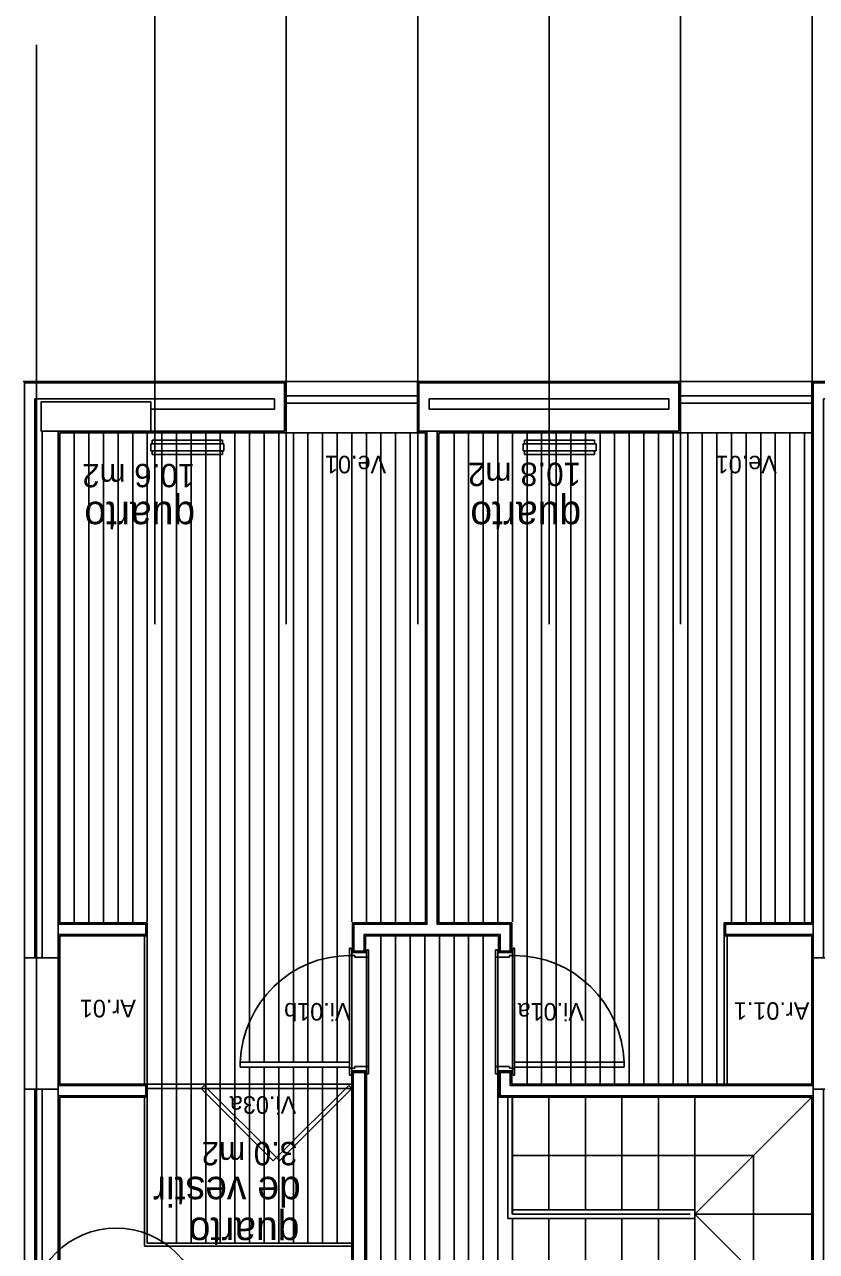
# Model space of a CAD drawing. Extents: x 1278 to 1356, y -253.7 to -224.
# Drawn here: x 1329.2 to 1334.62, y -237.88 to -229.48 of the extents above; entities that cross this region are included whole.
import ezdxf

# ---------------------------------------------------------------- set-up
doc = ezdxf.new("R2010")
doc.units = 0
for name, color, linetype in [('Level 1', 7, 'Continuous'), ('Level 10', 7, 'Continuous'), ('Level 13', 7, 'Continuous'), ('Level 2', 7, 'Continuous'), ('Level 4', 7, 'Continuous'), ('Level 40', 7, 'Continuous'), ('Level 60', 7, 'Continuous'), ('Level 65', 7, 'Continuous'), ('Level 66', 7, 'Continuous'), ('Level 67', 7, 'Continuous'), ('Level 69', 7, 'Continuous'), ('Level 70', 7, 'Continuous'), ('Level 93', 7, 'Continuous')]:
    doc.layers.add(name, color=color, linetype=linetype)

msp = doc.modelspace()

# ---------------------------------------------------------------- linework, layer by layer
at = {"layer": 'Level 1'}
for p, q in [((1330.9825, -231.934), (1330.9825, -232.2657)), ((1329.2718, -232.044), (1329.2718, -235.8713)), ((1330.9125, -232.1143), (1330.0668, -232.1143)), ((1330.9125, -232.044), (1330.9125, -232.1143)), ((1329.4325, -246.584), (1329.4325, -232.2657)), ((1330.9825, -232.2657), (1329.4325, -232.2657)), ((1331.9575, -232.2657), (1331.9575, -235.6407)), ((1332.0275, -235.6407), (1332.0275, -232.2657)), ((1330.0325, -235.6407), (1329.4325, -235.6407)), ((1330.0325, -235.7107), (1330.0325, -235.6407)), ((1331.9575, -235.6407), (1331.4575, -235.6407)), ((1331.4575, -235.6407), (1331.4575, -235.8257)), ((1332.5275, -235.6407), (1332.0275, -235.6407)), ((1332.5275, -235.8257), (1332.5275, -235.6407)), ((1334.6025, -235.6407), (1334.0025, -235.6407)), ((1334.0025, -235.6407), (1334.0025, -235.7107)), ((1329.4325, -235.7107), (1330.0325, -235.7107)), ((1331.5275, -235.7107), (1332.4575, -235.7107)), ((1331.5275, -235.8257), (1331.5275, -235.7107)), ((1332.4575, -235.7107), (1332.4575, -235.8257)), ((1334.0025, -235.7107), (1334.6025, -235.7107)), ((1331.4475, -235.8257), (1331.5375, -235.8257)), ((1332.5375, -235.8257), (1332.4475, -235.8257)), ((1331.4425, -236.6557), (1331.5425, -236.6557)), ((1331.4525, -236.6557), (1331.4525, -238.4357)), ((1331.5325, -238.4357), (1331.5325, -236.6557)), ((1332.5375, -236.6557), (1332.4475, -236.6557)), ((1332.4575, -236.6557), (1332.4575, -236.8157)), ((1332.5275, -236.6557), (1332.5275, -236.7457)), ((1329.2718, -236.7713), (1329.2718, -242.1713)), ((1329.3225, -242.1713), (1329.3225, -236.7713)), ((1330.0325, -236.7457), (1329.4325, -236.7457)), ((1329.4325, -236.8157), (1330.0325, -236.8157)), ((1330.0325, -236.8157), (1330.0325, -236.7457)), ((1332.4575, -236.8157), (1334.6025, -236.8157)), ((1332.5275, -236.7457), (1334.6025, -236.7457))]:
    msp.add_line(p, q, dxfattribs=at)
at = {"layer": 'Level 10'}
for p, q in [((1329.5425, -232.2757), (1329.5425, -235.6307)), ((1329.6425, -232.2757), (1329.6425, -235.6307)), ((1329.7425, -232.2757), (1329.7425, -235.6307)), ((1329.8425, -232.2757), (1329.8425, -235.6307)), ((1329.9425, -232.2757), (1329.9425, -235.6307)), ((1330.0425, -232.2757), (1330.0425, -235.6257)), ((1330.1425, -232.2757), (1330.1425, -237.8257)), ((1330.2425, -232.2757), (1330.2425, -237.8257)), ((1330.3425, -232.2757), (1330.3425, -237.8257)), ((1330.4425, -232.2757), (1330.4425, -237.8257)), ((1330.5425, -232.2757), (1330.5425, -237.8257)), ((1330.6425, -232.2757), (1330.6425, -237.8257)), ((1330.7425, -232.2757), (1330.7425, -236.5857)), ((1330.8425, -232.2757), (1330.8425, -236.5857)), ((1330.9425, -232.2757), (1330.9425, -236.5857)), ((1331.0425, -232.2757), (1331.0425, -236.5857)), ((1331.1425, -232.2757), (1331.1425, -236.5857)), ((1331.2425, -232.2757), (1331.2425, -236.5857)), ((1331.3425, -232.2757), (1331.3425, -236.5857)), ((1331.4425, -232.2757), (1331.4425, -235.6257)), ((1331.5425, -232.2757), (1331.5425, -235.6257)), ((1331.6425, -232.2757), (1331.6425, -235.6257)), ((1331.7425, -232.2757), (1331.7425, -235.6257)), ((1331.8425, -232.2757), (1331.8425, -235.6257)), ((1332.1425, -235.6257), (1332.1425, -232.2757)), ((1332.2425, -235.6257), (1332.2425, -232.2757)), ((1332.3425, -235.6257), (1332.3425, -232.2757)), ((1332.4425, -235.6257), (1332.4425, -232.2757)), ((1332.5425, -235.6257), (1332.5425, -232.2757)), ((1332.6425, -232.2757), (1332.6425, -236.7357)), ((1332.7425, -232.2757), (1332.7425, -236.7357)), ((1332.8425, -232.2757), (1332.8425, -236.7357)), ((1332.9425, -232.2757), (1332.9425, -236.7357)), ((1333.0425, -232.2757), (1333.0425, -236.7357)), ((1333.1425, -232.2757), (1333.1425, -236.7357)), ((1333.2425, -232.2757), (1333.2425, -236.7357)), ((1333.3425, -232.2757), (1333.3425, -236.7357)), ((1333.4425, -232.2757), (1333.4425, -236.7357)), ((1333.5425, -232.2757), (1333.5425, -236.7357)), ((1333.6425, -232.2757), (1333.6425, -236.7357)), ((1333.7425, -232.2757), (1333.7425, -236.7357)), ((1333.8425, -232.2757), (1333.8425, -236.7357)), ((1333.9425, -232.2757), (1333.9425, -236.7357)), ((1334.0425, -232.2757), (1334.0425, -235.6257)), ((1334.1425, -232.2757), (1334.1425, -235.6257)), ((1334.2425, -232.2757), (1334.2425, -235.6257)), ((1334.3425, -232.2757), (1334.3425, -235.6257)), ((1334.4425, -232.2757), (1334.4425, -235.6257)), ((1334.5425, -232.2757), (1334.5425, -235.6257)), ((1331.6425, -235.7207), (1331.6425, -238.4107)), ((1331.7425, -235.7207), (1331.7425, -238.4257)), ((1331.8425, -235.7207), (1331.8425, -238.4257)), ((1331.9425, -235.7207), (1331.9425, -238.4257)), ((1332.0425, -235.7207), (1332.0425, -238.4257)), ((1332.1425, -235.7207), (1332.1425, -238.4257)), ((1332.2425, -235.7207), (1332.2425, -238.4257)), ((1332.3425, -235.7207), (1332.3425, -238.4107)), ((1331.4425, -235.8557), (1331.4425, -236.6257)), ((1331.5425, -235.8657), (1331.5425, -236.6157)), ((1332.4425, -235.8657), (1332.4425, -236.6157)), ((1332.5425, -235.8557), (1332.5425, -236.6257)), ((1330.7425, -236.6207), (1330.7425, -237.8257)), ((1330.8425, -236.6207), (1330.8425, -237.8257)), ((1330.9425, -236.6207), (1330.9425, -237.8257)), ((1331.0425, -236.6207), (1331.0425, -237.8257)), ((1331.1425, -236.6207), (1331.1425, -237.8257)), ((1331.2425, -236.6207), (1331.2425, -237.8257)), ((1331.3425, -236.6207), (1331.3425, -237.8257)), ((1332.4425, -236.6557), (1332.4425, -238.4257))]:
    msp.add_line(p, q, dxfattribs=at)
at = {"layer": 'Level 13'}
for p, q in [((1330.0225, -236.7357), (1330.0225, -235.7207)), ((1330.0425, -236.7357), (1330.0425, -235.7207)), ((1333.9925, -236.7357), (1333.9925, -235.7207)), ((1334.0125, -236.7357), (1334.0125, -235.7207)), ((1331.4275, -235.8057), (1331.4275, -235.8557)), ((1331.4375, -235.8057), (1331.4275, -235.8057)), ((1331.4375, -235.8107), (1331.4375, -235.8057)), ((1331.4425, -235.8107), (1331.4375, -235.8107)), ((1331.4425, -235.8557), (1331.4425, -235.8107)), ((1331.5425, -235.8657), (1331.5425, -235.8207)), ((1331.5425, -235.8207), (1331.5475, -235.8207)), ((1331.5475, -235.8207), (1331.5475, -235.8157)), ((1331.5475, -235.8157), (1331.5575, -235.8157)), ((1331.5575, -235.8157), (1331.5575, -235.8657)), ((1332.4275, -235.8157), (1332.4275, -235.8657)), ((1332.4375, -235.8157), (1332.4275, -235.8157)), ((1332.4375, -235.8207), (1332.4375, -235.8157)), ((1332.4425, -235.8207), (1332.4375, -235.8207)), ((1332.4425, -235.8657), (1332.4425, -235.8207)), ((1332.5425, -235.8557), (1332.5425, -235.8107)), ((1332.5425, -235.8107), (1332.5475, -235.8107)), ((1332.5475, -235.8107), (1332.5475, -235.8057)), ((1332.5475, -235.8057), (1332.5575, -235.8057)), ((1332.5575, -235.8057), (1332.5575, -235.8557)), ((1331.4275, -235.8557), (1331.4425, -235.8557)), ((1331.4425, -235.8357), (1331.5425, -235.8357)), ((1331.4425, -235.8557), (1331.4425, -235.8357)), ((1331.4625, -235.8557), (1331.4425, -235.8557)), ((1331.4625, -235.8657), (1331.4625, -235.8557)), ((1331.5425, -235.8657), (1331.4625, -235.8657)), ((1331.5425, -235.8357), (1331.5425, -235.8657)), ((1331.5575, -235.8657), (1331.5425, -235.8657)), ((1332.4275, -235.8657), (1332.4425, -235.8657)), ((1332.5425, -235.8357), (1332.4425, -235.8357)), ((1332.4425, -235.8357), (1332.4425, -235.8657)), ((1332.4425, -235.8657), (1332.5225, -235.8657)), ((1332.5225, -235.8657), (1332.5225, -235.8557)), ((1332.5225, -235.8557), (1332.5425, -235.8557)), ((1332.5425, -235.8557), (1332.5425, -235.8357)), ((1332.5575, -235.8557), (1332.5425, -235.8557)), ((1331.4275, -236.5857), (1330.6775, -236.5857)), ((1330.6775, -236.5857), (1330.6775, -236.6207)), ((1330.6775, -236.6207), (1331.4275, -236.6207)), ((1331.4275, -236.6207), (1331.4275, -236.5857)), ((1331.4275, -236.6757), (1331.4275, -236.6257)), ((1331.4275, -236.6257), (1331.4425, -236.6257)), ((1331.4625, -236.6257), (1331.4425, -236.6257)), ((1331.4425, -236.6257), (1331.4425, -236.6457)), ((1331.4425, -236.6257), (1331.4425, -236.6707)), ((1331.4425, -236.6457), (1331.5425, -236.6457)), ((1331.5425, -236.6157), (1331.4625, -236.6157)), ((1331.4625, -236.6157), (1331.4625, -236.6257)), ((1331.5425, -236.6457), (1331.5425, -236.6157)), ((1331.5575, -236.6157), (1331.5425, -236.6157)), ((1331.5425, -236.6157), (1331.5425, -236.6607)), ((1331.5425, -236.6607), (1331.5475, -236.6607)), ((1331.5475, -236.6607), (1331.5475, -236.6657)), ((1331.5575, -236.6657), (1331.5575, -236.6157)), ((1332.4275, -236.6657), (1332.4275, -236.6157)), ((1332.4275, -236.6157), (1332.4425, -236.6157)), ((1332.4425, -236.6607), (1332.4375, -236.6607)), ((1332.4375, -236.6607), (1332.4375, -236.6657)), ((1332.4425, -236.6157), (1332.4425, -236.6607)), ((1332.4425, -236.6457), (1332.4425, -236.6157)), ((1332.4425, -236.6157), (1332.5225, -236.6157)), ((1332.5425, -236.6457), (1332.4425, -236.6457)), ((1332.5225, -236.6157), (1332.5225, -236.6257)), ((1332.5225, -236.6257), (1332.5425, -236.6257)), ((1332.5425, -236.6257), (1332.5425, -236.6457)), ((1332.5575, -236.6257), (1332.5425, -236.6257)), ((1332.5425, -236.6257), (1332.5425, -236.6707)), ((1332.5575, -236.6207), (1332.5575, -236.5857)), ((1332.5575, -236.5857), (1333.3075, -236.5857)), ((1333.3075, -236.6207), (1332.5575, -236.6207)), ((1332.5575, -236.6757), (1332.5575, -236.6257)), ((1333.3075, -236.5857), (1333.3075, -236.6207)), ((1330.4102, -236.7657), (1330.4314, -236.7445)), ((1330.4314, -236.7445), (1330.9264, -237.2395)), ((1331.4213, -236.7445), (1330.9264, -237.2395)), ((1331.4425, -236.7657), (1331.4213, -236.7445)), ((1331.4375, -236.6757), (1331.4275, -236.6757)), ((1331.4425, -236.6707), (1331.4375, -236.6707)), ((1331.4375, -236.6707), (1331.4375, -236.6757)), ((1331.5475, -236.6657), (1331.5575, -236.6657)), ((1332.4375, -236.6657), (1332.4275, -236.6657)), ((1332.5425, -236.6707), (1332.5475, -236.6707)), ((1332.5475, -236.6707), (1332.5475, -236.6757)), ((1332.5475, -236.6757), (1332.5575, -236.6757)), ((1330.0225, -237.8457), (1330.0225, -236.8257)), ((1330.0425, -237.8257), (1330.0425, -236.8257)), ((1330.4102, -236.7657), (1330.9051, -237.2607)), ((1331.4425, -236.7657), (1330.9476, -237.2607)), ((1330.9051, -237.2607), (1330.9264, -237.2395)), ((1330.9476, -237.2607), (1330.9264, -237.2395)), ((1331.4425, -237.8257), (1330.0425, -237.8257)), ((1331.4425, -237.8457), (1330.0225, -237.8457))]:
    msp.add_line(p, q, dxfattribs=at)
at = {"layer": 'Level 2'}
for p, q in [((1331.8925, -231.924), (1330.9925, -231.924)), ((1334.5925, -231.924), (1333.6925, -231.924)), ((1331.8925, -232.024), (1330.9925, -232.024)), ((1334.5925, -232.024), (1333.6925, -232.024)), ((1331.8925, -232.074), (1330.9925, -232.074)), ((1334.5925, -232.074), (1333.6925, -232.074)), ((1331.8925, -232.2757), (1330.9925, -232.2757)), ((1334.5925, -232.2757), (1333.6925, -232.2757)), ((1332.5118, -237.6557), (1332.5118, -236.8257)), ((1332.5418, -237.6257), (1332.5418, -236.8257)), ((1332.5425, -237.6257), (1332.5425, -236.8257)), ((1332.7925, -237.5957), (1332.7925, -236.8257)), ((1333.0425, -237.5957), (1333.0425, -236.8257)), ((1333.2925, -237.5957), (1333.2925, -236.8257)), ((1333.5425, -237.5957), (1333.5425, -236.8257)), ((1333.7925, -237.5957), (1333.7925, -236.8257)), ((1333.7925, -237.6257), (1334.5925, -236.8257)), ((1332.5425, -237.2257), (1334.1925, -237.2257)), ((1334.1925, -238.0257), (1334.1925, -237.2257)), ((1333.7925, -237.6557), (1332.5118, -237.6557)), ((1333.7925, -237.5957), (1332.5425, -237.5957)), ((1333.7605, -237.6257), (1332.5425, -237.6257)), ((1332.5425, -238.424), (1332.5425, -237.6557)), ((1332.7925, -238.424), (1332.7925, -237.654)), ((1333.0425, -238.424), (1333.0425, -237.654)), ((1333.2925, -237.654), (1333.2925, -238.424)), ((1333.5425, -237.654), (1333.5425, -238.424)), ((1333.7925, -237.6557), (1333.7925, -237.5957)), ((1334.5925, -237.6257), (1333.7925, -237.6257)), ((1333.7925, -237.6257), (1334.5925, -238.4257)), ((1333.7925, -238.4257), (1333.7925, -237.6557))]:
    msp.add_line(p, q, dxfattribs=at)
at = {"layer": 'Level 4'}
for p, q in [((1331.4275, -235.8557), (1331.4275, -236.5857)), ((1331.5575, -236.6157), (1331.5575, -235.8657)), ((1332.4275, -236.6157), (1332.4275, -235.8657)), ((1332.5575, -235.8557), (1332.5575, -236.5857)), ((1330.0425, -236.7357), (1331.4425, -236.7357)), ((1330.0425, -236.7657), (1331.4425, -236.7657))]:
    msp.add_line(p, q, dxfattribs=at)
for centre, start_param, end_param in [((1331.4275, -236.6189), 3.141593, 4.668897), ((1332.5575, -236.6189), 1.614288, 3.141593)]:
    msp.add_ellipse(centre, major_axis=(0, -0.7632), ratio=0.982661, start_param=start_param, end_param=end_param, dxfattribs=at)
at = {"layer": 'Level 65'}
for p, q in [((1330.9925, -231.924), (1329.1918, -231.924)), ((1330.9925, -231.924), (1330.9925, -232.2757)), ((1331.8925, -232.2757), (1331.8925, -231.924)), ((1333.6925, -231.924), (1331.8925, -231.924)), ((1333.6925, -231.924), (1333.6925, -232.2757)), ((1336.3933, -231.924), (1334.5925, -231.924)), ((1334.5925, -235.6307), (1334.5925, -231.924)), ((1330.9925, -232.2757), (1329.4425, -232.2757)), ((1329.4425, -235.6307), (1329.4425, -232.2757)), ((1331.9475, -232.2757), (1331.8925, -232.2757)), ((1331.9475, -232.2757), (1331.9475, -235.6307)), ((1332.0375, -235.6307), (1332.0375, -232.2757)), ((1333.6925, -232.2757), (1332.0375, -232.2757)), ((1330.0425, -235.6307), (1329.4425, -235.6307)), ((1330.0425, -235.7207), (1330.0425, -235.6307)), ((1331.9475, -235.6307), (1331.4475, -235.6307)), ((1331.4475, -235.6307), (1331.4475, -235.8257)), ((1332.5375, -235.6307), (1332.0375, -235.6307)), ((1332.5375, -235.8257), (1332.5375, -235.6307)), ((1334.5925, -235.6307), (1333.9925, -235.6307)), ((1333.9925, -235.6307), (1333.9925, -235.7207)), ((1329.4425, -236.7357), (1329.4425, -235.7207)), ((1329.4425, -235.7207), (1330.0425, -235.7207)), ((1331.5375, -235.8257), (1331.5375, -235.7207)), ((1331.5375, -235.7207), (1332.4475, -235.7207)), ((1332.4475, -235.7207), (1332.4475, -235.8257)), ((1333.9925, -235.7207), (1334.5925, -235.7207)), ((1334.5925, -236.7357), (1334.5925, -235.7207)), ((1334.5925, -236.7357), (1334.5925, -235.7207)), ((1331.4425, -236.6557), (1331.4425, -238.4257)), ((1331.5425, -238.4257), (1331.5425, -236.6557)), ((1332.4475, -236.6557), (1332.4475, -236.8257)), ((1332.5375, -236.6557), (1332.5375, -236.7357)), ((1330.0425, -236.7357), (1329.4425, -236.7357)), ((1330.0425, -236.8257), (1330.0425, -236.7357)), ((1334.5925, -236.7357), (1332.5375, -236.7357)), ((1329.4425, -236.8257), (1330.0425, -236.8257)), ((1332.4475, -236.8257), (1334.5925, -236.8257)), ((1334.5925, -238.4257), (1334.5925, -236.8257)), ((1334.5925, -238.4257), (1334.5925, -236.8257))]:
    msp.add_line(p, q, dxfattribs=at)
msp.add_lwpolyline([(1329.4425, -238.164), (1329.4425, -236.8257)], dxfattribs=at)
at = {"layer": 'Level 66'}
for p, q in [((1330.9825, -231.934), (1329.2018, -231.934)), ((1333.6825, -231.934), (1331.9025, -231.934)), ((1331.9025, -231.934), (1331.9025, -232.2657)), ((1333.6825, -232.2657), (1333.6825, -231.934)), ((1336.3833, -231.934), (1334.6025, -231.934)), ((1334.6025, -235.6407), (1334.6025, -231.934)), ((1330.9125, -232.044), (1329.2718, -232.044)), ((1330.0668, -232.0639), (1329.3168, -232.0639)), ((1329.3168, -232.0639), (1329.3168, -232.2657)), ((1330.0668, -232.1143), (1330.0668, -232.0639)), ((1331.9725, -232.114), (1331.9725, -232.044)), ((1331.9725, -232.044), (1333.6125, -232.044)), ((1333.6125, -232.114), (1331.9725, -232.114)), ((1333.6125, -232.044), (1333.6125, -232.114)), ((1329.3225, -235.8713), (1329.3225, -232.2657)), ((1331.9025, -232.2657), (1333.6825, -232.2657)), ((1330.5668, -232.3507), (1330.0668, -232.3507)), ((1330.0668, -232.4007), (1330.0668, -232.3507)), ((1330.5568, -232.3257), (1330.0768, -232.3257)), ((1330.0768, -232.3507), (1330.0768, -232.3257)), ((1330.5568, -232.3507), (1330.5568, -232.3257)), ((1330.5668, -232.4007), (1330.5668, -232.3507)), ((1333.115, -232.3507), (1332.615, -232.3507)), ((1332.615, -232.4007), (1332.615, -232.3507)), ((1333.105, -232.3257), (1332.625, -232.3257)), ((1332.625, -232.3507), (1332.625, -232.3257)), ((1333.105, -232.3507), (1333.105, -232.3257)), ((1333.115, -232.4007), (1333.115, -232.3507)), ((1330.5668, -232.4007), (1330.0668, -232.4007)), ((1330.0768, -232.4257), (1330.0768, -232.4007)), ((1330.0768, -232.4257), (1330.5568, -232.4257)), ((1330.5568, -232.4257), (1330.5568, -232.4007)), ((1333.115, -232.4007), (1332.615, -232.4007)), ((1332.625, -232.4257), (1332.625, -232.4007)), ((1332.625, -232.4257), (1333.105, -232.4257)), ((1333.105, -232.4257), (1333.105, -232.4007)), ((1334.6025, -236.7457), (1334.6025, -235.7107)), ((1334.6025, -238.4357), (1334.6025, -236.8157))]:
    msp.add_line(p, q, dxfattribs=at)
for points in [[(1330.0668, -232.0639), (1329.3168, -232.0639), (1329.3168, -232.2657), (1330.0668, -232.2657)], [(1329.2018, -235.8713), (1329.4318, -235.8713), (1329.4318, -236.7713), (1329.2018, -236.7713)], [(1334.6025, -235.8713), (1334.8325, -235.8713), (1334.8325, -236.7713), (1334.6025, -236.7713)]]:
    msp.add_lwpolyline(points, close=True, dxfattribs=at)
at = {"layer": 'Level 67'}
for points in [[(1330.9825, -232.2657), (1330.9825, -231.934), (1329.2018, -231.934), (1329.2018, -235.8713), (1329.2718, -235.8713), (1329.2718, -232.044), (1330.9125, -232.044), (1330.9125, -232.1143), (1330.0668, -232.1143), (1330.0668, -232.2657)], [(1335.4675, -232.1143), (1335.4675, -232.2657), (1336.3833, -232.2657), (1336.3833, -231.934), (1334.6025, -231.934), (1334.6025, -235.8713), (1334.6725, -235.8713), (1334.6725, -232.044), (1336.3133, -232.044), (1336.3133, -232.1143)], [(1330.0325, -235.6407), (1330.0325, -235.7107), (1329.4325, -235.7107), (1329.4325, -235.8713), (1329.3225, -235.8713), (1329.3225, -232.2657), (1329.4325, -232.2657), (1329.4325, -235.6407)], [(1332.5275, -235.8257), (1332.5275, -235.6407), (1332.0275, -235.6407), (1332.0275, -232.2709), (1332.0275, -232.2657), (1331.9575, -232.2657), (1331.9575, -235.6407), (1331.4575, -235.6407), (1331.4575, -235.8257), (1331.5275, -235.8257), (1331.5275, -235.7107), (1332.4575, -235.7107), (1332.4575, -235.8257)], [(1334.6025, -235.6407), (1334.6025, -235.7107), (1334.0025, -235.7107), (1334.0025, -235.6407)], [(1334.6025, -240.234), (1334.6025, -240.304), (1332.5125, -240.304), (1332.5125, -239.4057), (1331.5125, -239.4057), (1331.5125, -238.5057), (1330.3525, -238.5057), (1330.3525, -238.244), (1329.4325, -238.244), (1329.4325, -238.174), (1330.4233, -238.174), (1330.4233, -238.4357), (1331.4525, -238.4357), (1331.4525, -236.6557), (1331.5325, -236.6557), (1331.5325, -238.4357), (1331.6212, -238.4357), (1331.6175, -238.4357), (1331.6175, -238.5057), (1331.5825, -238.5057), (1331.5825, -239.3357), (1332.5825, -239.3357), (1332.5825, -240.234), (1334.6025, -240.234)], [(1334.6025, -236.7457), (1332.5275, -236.7457), (1332.5275, -236.6557), (1332.4575, -236.6557), (1332.4575, -236.8157), (1334.6025, -236.8157)], [(1329.2018, -242.1713), (1329.2718, -242.1713), (1329.2718, -236.7713), (1329.2018, -236.7713)], [(1329.4318, -236.7713), (1329.3225, -236.7713), (1329.3225, -242.1713), (1329.4325, -242.1713), (1329.4325, -242.109), (1330.0325, -242.109), (1330.0325, -242.039), (1329.4325, -242.039), (1329.4318, -236.7713)], [(1329.4325, -236.7457), (1330.0325, -236.7457), (1330.0325, -236.8157), (1329.4403, -236.8157), (1329.4325, -236.8157)], [(1334.6725, -242.1713), (1334.6025, -242.1713), (1334.6025, -242.104), (1332.5275, -242.104), (1332.5275, -242.194), (1332.4575, -242.194), (1332.4575, -242.034), (1334.6025, -242.034), (1334.6025, -236.7713), (1334.6725, -236.7713)]]:
    msp.add_lwpolyline(points, close=True, dxfattribs=at)
at = {"layer": 'Level 69'}
msp.add_circle((1329.8293, -238.3059), 0.5842, dxfattribs=at)
at = {"layer": 'Level 70'}
msp.add_line((1329.284, -250.7923), (1329.284, -229.6198), dxfattribs=at)
at = {"layer": 'Level 93'}
for p, q in [((1330.094, -233.587), (1330.094, -228.3936)), ((1330.994, -233.587), (1330.994, -228.3936)), ((1331.894, -233.587), (1331.894, -228.3936)), ((1332.794, -233.587), (1332.794, -228.3936)), ((1333.694, -233.587), (1333.694, -228.3936)), ((1334.594, -233.587), (1334.594, -228.3936))]:
    msp.add_line(p, q, dxfattribs=at)

# ---------------------------------------------------------------- texts
at = {"layer": 'Level 40'}
for s, rotation, p in [('Ve.01', 180.00001, (1331.678, -232.4335)), ('Ve.01', 180.00001, (1334.3535, -232.4335)), ('Ar.01', 179.99999, (1329.9641, -236.1586)), ('Vi.01b', 180.00001, (1331.4343, -236.1806)), ('Vi.01a', 180.00001, (1333.0324, -236.1806)), ('Ar.01.1', 179.99999, (1334.5756, -236.1751)), ('Vi.03a', 180.00001, (1331.0623, -236.8188))]:
    msp.add_text(s, height=0.12, rotation=rotation, dxfattribs=at).set_placement(p)
at = {"layer": 'Level 60'}
for s, height, p in [('10.6 m2', 0.16, (1330.37, -232.4888)), ('10.8 m2', 0.16, (1333.0117, -232.4804)), ('quarto', 0.2, (1330.37, -232.7482)), ('quarto', 0.2, (1333.013, -232.7482)), ('3.0 m2', 0.16, (1331.0688, -237.1316)), ('de vestir', 0.2, (1331.0929, -237.3705)), ('de vestir', 0.2, (1331.0929, -237.3705)), ('quarto', 0.2, (1331.0842, -237.6501))]:
    msp.add_text(s, height=height, rotation=180, dxfattribs=at).set_placement(p)

doc.saveas('drawing.dxf')
